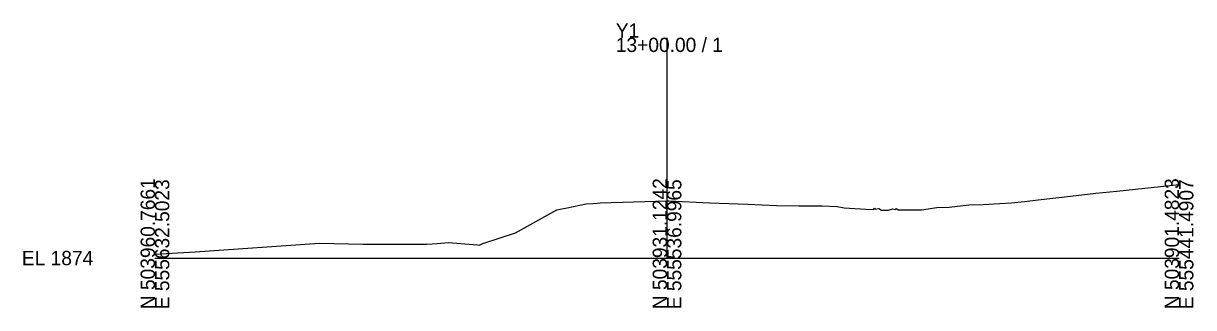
# Model space of a CAD drawing. Extents: x -26 to 203, y -10 to 5015.
# Drawn here: x -25.7 to 202.8, y 2990.3 to 3045.9 of the extents above; entities that cross this region are included whole.
import ezdxf

# ---------------------------------------------------------------- set-up
doc = ezdxf.new("R2010")
doc.units = 0
doc.layers.add('Exist Cross Section Cell', color=7, linetype='Continuous')
doc.layers.add('Exist XS Ground Line', color=7, linetype='Continuous')

msp = doc.modelspace()

# ---------------------------------------------------------------- linework, layer by layer
at = {"layer": 'Exist Cross Section Cell'}
for p, q in [((100, 3000), (100, 3043.1)), ((0, 3000), (100, 3000)), ((100, 3000), (200, 3000))]:
    msp.add_line(p, q, dxfattribs=at)
at = {"layer": 'Exist XS Ground Line'}
for p, q in [((187.84, 3013.09), (200, 3014.37)), ((172.51, 3011.38), (178.83, 3012.11)), ((178.83, 3012.11), (183.72, 3012.68)), ((183.72, 3012.68), (187.84, 3013.09)), ((79.47, 3009.61), (80.47, 3009.8)), ((80.47, 3009.8), (84.23, 3010.58)), ((84.23, 3010.58), (85.57, 3010.68)), ((85.57, 3010.68), (86.38, 3010.75)), ((86.38, 3010.75), (86.96, 3010.79)), ((86.96, 3010.79), (93.44, 3011.01)), ((93.44, 3011.01), (100, 3011.2)), ((100, 3011.2), (100.39, 3011.21)), ((100.39, 3011.21), (108.29, 3010.82)), ((108.29, 3010.82), (115.76, 3010.53)), ((115.76, 3010.53), (121.4, 3010.3)), ((121.4, 3010.3), (125.75, 3010.23)), ((125.75, 3010.23), (126.89, 3010.21)), ((126.89, 3010.21), (130.27, 3010.19)), ((130.27, 3010.19), (133.25, 3010.09)), ((133.25, 3010.09), (134.63, 3009.84)), ((134.63, 3009.84), (138.83, 3009.57)), ((149.72, 3009.45), (152.71, 3009.9)), ((152.71, 3009.9), (155.08, 3009.97)), ((155.08, 3009.97), (158.97, 3010.4)), ((158.97, 3010.4), (161.73, 3010.5)), ((161.73, 3010.5), (165.03, 3010.68)), ((165.03, 3010.68), (167.27, 3010.83)), ((167.27, 3010.83), (169.83, 3011.09)), ((169.83, 3011.09), (172.51, 3011.38)), ((70.42, 3004.93), (78.49, 3009.45)), ((78.49, 3009.45), (79.47, 3009.61)), ((138.83, 3009.57), (140.3, 3009.49)), ((140.3, 3009.49), (140.52, 3009.74)), ((140.52, 3009.74), (140.65, 3009.56)), ((140.65, 3009.56), (141.34, 3009.69)), ((141.34, 3009.69), (141.89, 3009.36)), ((141.89, 3009.36), (143.27, 3009.36)), ((143.27, 3009.36), (144.03, 3009.65)), ((144.03, 3009.65), (144.69, 3009.5)), ((144.69, 3009.5), (144.85, 3009.71)), ((144.85, 3009.71), (145.15, 3009.42)), ((145.15, 3009.42), (148.11, 3009.43)), ((148.11, 3009.43), (149.72, 3009.45)), ((55.11, 3002.84), (57.31, 3003.04)), ((57.31, 3003.04), (62.13, 3002.65)), ((64.01, 3002.86), (70.42, 3004.93)), ((0, 3000.78), (7.86, 3001.23)), ((7.86, 3001.23), (32.13, 3002.9)), ((32.13, 3002.9), (40.61, 3002.7)), ((40.61, 3002.7), (41.75, 3002.74)), ((41.75, 3002.74), (46.63, 3002.69)), ((46.63, 3002.69), (53.08, 3002.7)), ((53.08, 3002.7), (55.11, 3002.84)), ((62.13, 3002.65), (62.99, 3002.57)), ((62.99, 3002.57), (63.3, 3002.55)), ((63.3, 3002.55), (64.01, 3002.86))]:
    msp.add_line(p, q, dxfattribs=at)

# ---------------------------------------------------------------- texts
at = {"layer": 'Exist Cross Section Cell'}
for s, p in [('Y1', (90, 3043.1)), ('13+00.00 / 1', (90, 3040.3)), ('EL 1874', (-26, 2998.6))]:
    msp.add_text(s, height=2.8, dxfattribs=at).set_placement(p)
for s, p in [('N 503960.7661', (0, 2990)), ('E 555632.5023', (2.8, 2990)), ('N 503931.1242', (100, 2990)), ('E 555536.9965', (102.8, 2990)), ('N 503901.4823', (200, 2990)), ('E 555441.4907', (202.8, 2990))]:
    msp.add_text(s, height=2.8, rotation=90, dxfattribs=at).set_placement(p)

doc.saveas('drawing.dxf')
